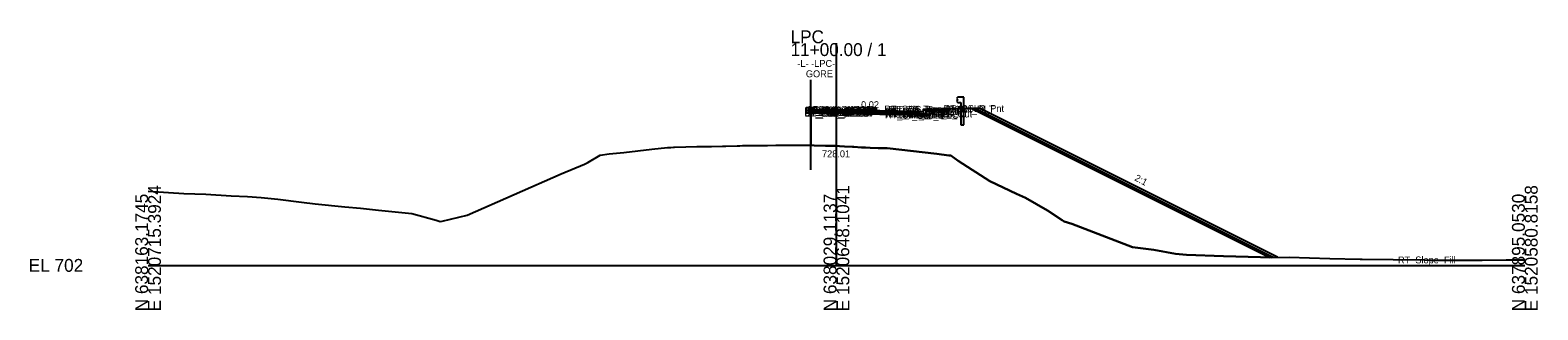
# Model space of a CAD drawing. Extents: x -26 to 303, y -10 to 4521.
# Drawn here: x -25.7 to 302.8, y 990.3 to 1051.3 of the extents above; entities that cross this region are included whole.
import ezdxf

# ---------------------------------------------------------------- set-up
doc = ezdxf.new("R2010")
doc.units = 0
for name, color, linetype in [('Default', 7, 'Continuous'), ('Exist Cross Section Cell', 7, 'Continuous'), ('Exist XS Center Line Elevation Label', 7, 'Continuous'), ('Exist XS Ground Line', 7, 'Continuous'), ('Old_Level_63', 7, 'Continuous'), ('Prop CMT Guardrail Graphics', 7, 'Continuous'), ('Prop CMT Pvmt Course 1', 7, 'Continuous'), ('Prop CMT Pvmt Course 1 CG', 7, 'Continuous'), ('Prop CMT Pvmt Course 2', 7, 'Continuous'), ('Prop CMT Pvmt Course 3', 7, 'Continuous'), ('Prop CMT Pvmt Surface', 7, 'Continuous'), ('Prop CMT Slope Grass', 7, 'Continuous'), ('Prop CMT Subgrade Earthwork', 7, 'Continuous'), ('Prop XS Earthwork Shape', 7, 'Continuous'), ('Prop XS Shear Point Element', 7, 'Continuous'), ('Prop XS Shear Point Label', 7, 'Continuous'), ('Scratch_Level_3', 7, 'Continuous')]:
    doc.layers.add(name, color=color, linetype=linetype)

msp = doc.modelspace()

# ---------------------------------------------------------------- linework, layer by layer
at = {"layer": 'Exist Cross Section Cell'}
for p, q in [((150, 1000), (150, 1048.42)), ((0, 1000), (150, 1000)), ((150, 1000), (300, 1000))]:
    msp.add_line(p, q, dxfattribs=at)
at = {"layer": 'Exist XS Ground Line'}
msp.add_lwpolyline([(0, 1016.14), (7.82, 1015.67), (12.61, 1015.49), (18.09, 1015.19), (21.69, 1014.98), (24.62, 1014.77), (28.25, 1014.43), (33.45, 1013.81), (36.4, 1013.43), (42.85, 1012.76), (46.28, 1012.45), (50.18, 1012.06), (57.48, 1011.34), (62.79, 1009.84), (63.65, 1009.59), (64.07, 1009.67), (69.54, 1010.91), (90.04, 1019.93), (95.13, 1022.05), (95.8, 1022.4), (98.49, 1024.03), (100.5, 1024.28), (103.68, 1024.62), (109.8, 1025.33), (113.17, 1025.69), (113.31, 1025.71), (113.35, 1025.71), (113.91, 1025.72), (114.46, 1025.74), (114.54, 1025.74), (114.7, 1025.75), (117.16, 1025.83), (119.58, 1025.88), (119.96, 1025.89), (120.09, 1025.89), (120.34, 1025.89), (122.76, 1025.91), (125.17, 1025.97), (125.55, 1025.97), (125.93, 1025.99), (128.35, 1026.06), (128.98, 1026.08), (129.5, 1026.09), (130.98, 1026.1), (131.14, 1026.11), (131.49, 1026.11), (133.13, 1026.14), (133.95, 1026.15), (134.99, 1026.16), (136.76, 1026.17), (136.86, 1026.18), (137.07, 1026.18), (139.54, 1026.2), (142, 1026.2), (142.3, 1026.2), (142.55, 1026.2), (142.61, 1026.2), (144.31, 1026.18), (144.66, 1026.17), (145.12, 1026.14), (147.63, 1026.08), (147.91, 1026.07), (148.19, 1026.06), (149.86, 1026.02), (150.7, 1025.99), (151.73, 1025.94), (153.51, 1025.85), (153.59, 1025.85), (153.76, 1025.84), (155.46, 1025.72), (156.31, 1025.69), (157.32, 1025.65), (159.11, 1025.56), (159.24, 1025.56), (160.6, 1025.54), (161.05, 1025.53), (171.87, 1024.28), (174.46, 1023.98), (174.91, 1023.93), (176.51, 1022.82), (183.4, 1018.32), (189.22, 1015.57), (191.2, 1014.7), (195.96, 1011.97), (199.21, 1009.83), (199.65, 1009.57), (201.31, 1009.07), (214.49, 1003.98), (219.13, 1003.37), (223.86, 1002.53), (226.26, 1002.33), (234.37, 1002), (242.42, 1001.76), (244.86, 1001.75), (248.66, 1001.82), (257.48, 1001.52), (264.14, 1001.37), (264.35, 1001.36), (264.46, 1001.36), (264.56, 1001.36), (278.09, 1001.18), (279.27, 1001.17), (290.71, 1001.13), (295.95, 1001.18), (297.55, 1001.18), (298.32, 1001.21), (300, 1001.22)], dxfattribs=at)
at = {"layer": 'Old_Level_63'}
for p in [(169.51, 1033.68), (174.5, 1034.11)]:
    msp.add_line(p, (174.51, 1033.78), dxfattribs=at)
for points in [[(169.5, 1034.01), (169.5, 1033), (167, 1033.05)], [(167, 1033.63), (169, 1033.51)], [(167, 1033.05), (167, 1033.63)], [(167, 1033.38), (167, 1033.05)], [(169, 1033.51), (169, 1034.01), (169.5, 1034.01)]]:
    msp.add_lwpolyline(points, dxfattribs=at)
at = {"layer": 'Prop CMT Guardrail Graphics'}
for points in [[(177.78, 1036.66), (176.45, 1036.66), (176.18, 1036.37)], [(176.18, 1036.37), (176.45, 1036.08)], [(176.45, 1036.08), (176.18, 1035.79)], [(176.18, 1035.79), (176.45, 1035.5), (177.12, 1035.5)], [(177.12, 1035.5), (177.12, 1030.66)], [(177.78, 1030.66), (177.78, 1036.66)], [(177.12, 1030.66), (177.78, 1030.66)]]:
    msp.add_lwpolyline(points, dxfattribs=at)
at = {"layer": 'Prop CMT Pvmt Course 1'}
msp.add_line((144.4, 1034.08), (167, 1033.63), dxfattribs=at)
for points in [[(167, 1033.38), (144.4, 1033.83)], [(149.99, 1033.72), (150, 1033.72)], [(167, 1033.63), (167, 1033.38)]]:
    msp.add_lwpolyline(points, dxfattribs=at)
at = {"layer": 'Prop CMT Pvmt Course 1 CG'}
for points in [[(167, 1033.05), (170, 1032.99), (170.25, 1032.74)], [(167, 1032.8), (167, 1033.05)], [(170.25, 1032.74), (167, 1032.8)]]:
    msp.add_lwpolyline(points, dxfattribs=at)
at = {"layer": 'Prop CMT Pvmt Course 2'}
for points in [[(144.4, 1033.83), (167, 1033.38)], [(167, 1033.05), (144.4, 1033.5)], [(150, 1033.72), (149.99, 1033.72)]]:
    msp.add_lwpolyline(points, dxfattribs=at)
at = {"layer": 'Prop CMT Pvmt Course 3'}
for points in [[(144.4, 1033.5), (167, 1033.05)], [(167, 1032.8), (144.4, 1033.25)], [(167, 1033.05), (167, 1032.8)]]:
    msp.add_lwpolyline(points, dxfattribs=at)
at = {"layer": 'Prop CMT Pvmt Surface'}
msp.add_lwpolyline([(144.4, 1034.08), (167, 1033.63)], dxfattribs=at)
at = {"layer": 'Prop CMT Slope Grass'}
for points in [[(144.4, 1034.08), (144.4, 1026.18)], [(169.5, 1034.01), (179.5, 1034.21)], [(179.5, 1034.21), (244.42, 1001.75)]]:
    msp.add_lwpolyline(points, dxfattribs=at)
at = {"layer": 'Prop CMT Subgrade Earthwork'}
for points in [[(144.4, 1033.25), (167, 1032.8)], [(167, 1032.8), (170.25, 1032.74), (171.57, 1034.05)]]:
    msp.add_lwpolyline(points, dxfattribs=at)
at = {"layer": 'Prop XS Earthwork Shape'}
for points in [[(144.4, 1033.25), (144.4, 1026.18), (144.66, 1026.17), (145.12, 1026.14), (147.63, 1026.08), (147.91, 1026.07), (148.19, 1026.06), (149.86, 1026.02), (150.7, 1025.99), (151.73, 1025.94), (153.51, 1025.85), (153.76, 1025.84), (155.46, 1025.72), (156.31, 1025.69), (157.32, 1025.65), (159.11, 1025.56), (159.24, 1025.56), (160.6, 1025.54), (161.05, 1025.53), (171.87, 1024.28), (174.46, 1023.98), (174.91, 1023.93), (176.51, 1022.82), (183.4, 1018.32), (189.22, 1015.57), (191.2, 1014.7), (195.96, 1011.97), (199.21, 1009.83), (199.65, 1009.57), (201.31, 1009.07), (214.49, 1003.98), (219.13, 1003.37), (223.86, 1002.53), (226.26, 1002.33), (234.37, 1002), (242.42, 1001.76), (244.86, 1001.75), (246.13, 1001.77), (181.18, 1034.25), (174.5, 1034.11), (174.51, 1033.78), (171.23, 1033.71), (170.25, 1032.74), (167, 1032.8)], [(171.23, 1033.71), (174.51, 1033.78), (174.5, 1034.11), (180.24, 1034.23), (245.18, 1001.76), (244.86, 1001.75), (242.42, 1001.76), (234.37, 1002), (226.26, 1002.33), (223.86, 1002.53), (219.13, 1003.37), (214.49, 1003.98), (201.31, 1009.07), (199.65, 1009.57), (199.21, 1009.83), (195.96, 1011.97), (191.2, 1014.7), (189.22, 1015.57), (183.4, 1018.32), (176.51, 1022.82), (174.91, 1023.93), (174.46, 1023.98), (171.87, 1024.28), (161.05, 1025.53), (160.6, 1025.54), (159.24, 1025.56), (159.11, 1025.56), (157.32, 1025.65), (156.31, 1025.69), (155.46, 1025.72), (153.76, 1025.84), (153.51, 1025.85), (151.73, 1025.94), (150.7, 1025.99), (149.86, 1026.02), (148.19, 1026.06), (147.91, 1026.07), (147.63, 1026.08), (145.12, 1026.14), (144.66, 1026.17), (144.4, 1026.18), (144.4, 1033.25), (167, 1032.8), (170.25, 1032.74)]]:
    msp.add_lwpolyline(points, close=True, dxfattribs=at)
at = {"layer": 'Prop XS Shear Point Label'}
msp.add_line((144.4, 1020.81), (144.4, 1040.41), dxfattribs=at)
at = {"layer": 'Scratch_Level_3'}
msp.add_lwpolyline([(167, 1033.63), (169, 1033.51), (169, 1034.01), (169.5, 1034.01)], dxfattribs=at)

# ---------------------------------------------------------------- texts
at = {"layer": 'Default'}
msp.add_text('-', height=0.0001, dxfattribs=at).set_placement((0, 1000))
at = {"layer": 'Exist Cross Section Cell'}
for s, p in [('11+00.00 / 1', (140, 1045.62)), ('LPC', (140, 1048.42)), ('EL 702', (-26, 998.6))]:
    msp.add_text(s, height=2.8, dxfattribs=at).set_placement(p)
for s, p in [('N 638163.1745', (0, 990)), ('E 1520715.3924', (2.8, 990)), ('N 638029.1137', (150, 990)), ('E 1520648.1041', (152.8, 990)), ('N 637895.0530', (300, 990)), ('E 1520580.8158', (302.8, 990))]:
    msp.add_text(s, height=2.8, rotation=90, dxfattribs=at).set_placement(p)
at = {"layer": 'Exist XS Center Line Elevation Label'}
for s, p in [('-L- -LPC-', (141.48, 1043.25)), ('GORE', (143.34, 1041)), ('0.02', (155.37, 1034.28)), ('728.01', (146.85, 1023.56))]:
    msp.add_text(s, height=1.5, dxfattribs=at).set_placement(p)
msp.add_text('2:1', height=1.5, rotation=332.3479, dxfattribs=at).set_placement((214.81, 1018.59))
at = {"layer": 'Prop XS Shear Point Element'}
for s, p in [('RT_Sub_Trench_Out_DLT', (160.45, 1033.3)), ('RT_CSLP_Pnt', (173.36, 1033.45)), ('RT_PV2_OEEOP', (143, 1032.97)), ('RT_PV3_OEEOP', (143, 1032.64)), ('RT_Sub_OEEOP', (143.04, 1032.39)), ('LT_PV2_OEEOP', (143.09, 1032.97)), ('LT_PV3_OEEOP', (143.09, 1032.64)), ('LT_Sub_OEEOP', (143.12, 1032.39)), ('RT_PV1_OEEOP', (143.18, 1033.1)), ('LT_PV1_OEEOP', (143.27, 1033.1)), ('RT_PV2_IEEOP', (143.57, 1032.97)), ('LT_PV2_OEOT', (143.61, 1032.97)), ('LT_PV3_OEOT', (143.61, 1032.64)), ('LT_Sub_OEOT', (143.64, 1032.39)), ('LT_PV2_IEEOP', (143.66, 1032.97)), ('RT_PV1_IEEOP', (143.75, 1033.1)), ('LT_PV1_OEOT', (143.79, 1033.22)), ('LT_PV1_IEEOP', (143.84, 1033.1)), ('PV2_PGL', (146.03, 1032.97)), ('PV1_PGL', (146.2, 1033.22)), ('RT_PV2_OEOT', (160.53, 1032.63)), ('RT_PV3_OEOT', (160.53, 1032.3)), ('RT_Sub_OEOT', (160.56, 1032.05)), ('RT_PV1_OEOT', (160.71, 1032.88)), ('RT_CG_Bot_IE', (160.79, 1032.3)), ('RT_CG_Top_Face', (161.29, 1033.26)), ('RT_CG1_Shelf_Out', (161.64, 1032.24)), ('RT_CG_Top_Gut', (161.69, 1032.76)), ('RT_CG_Top_BOC', (161.77, 1033.26)), ('RT_CG_Bot_BOC', (161.98, 1032.25)), ('RT_Sub_OEOP', (163.81, 1031.99)), ('RT_Slope_Fill', (272.35, 1000.43))]:
    msp.add_text(s, height=1.5, dxfattribs=at).set_placement(p)

doc.saveas('drawing.dxf')
